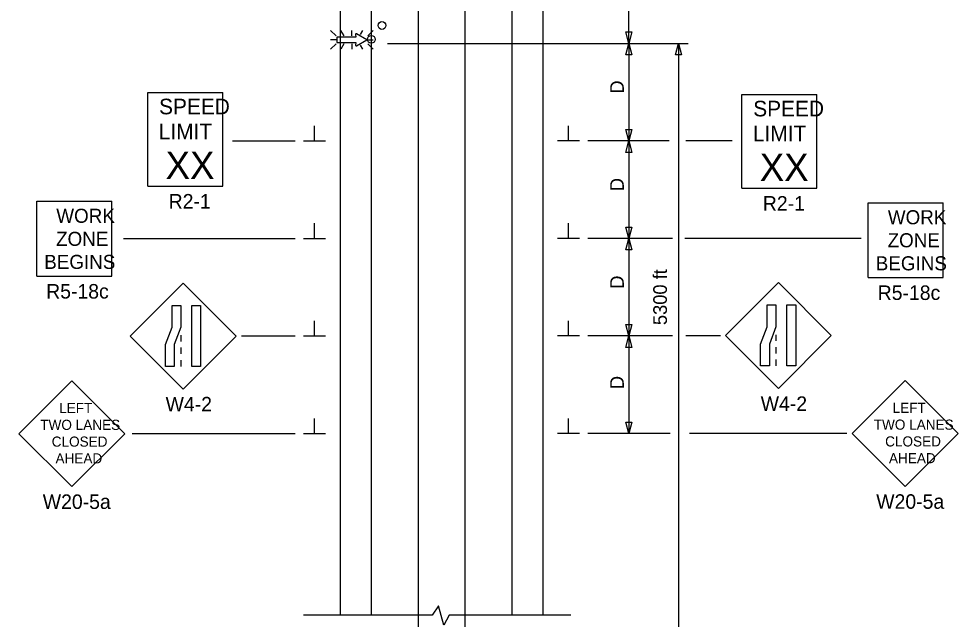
# Model space of a CAD drawing. Extents: x 16794 to 19504, y 7009 to 8243.
# Drawn here: x 17851.7 to 18333.2, y 7552.3 to 7860.1 of the extents above; entities that cross this region are included whole.
import ezdxf

# ---------------------------------------------------------------- set-up
doc = ezdxf.new("R2010")
doc.units = 0
for name, color, linetype in [('ALI_LEGAL_EX', 7, 'Continuous'), ('PAVT_EDGE_EX', 7, 'Continuous'), ('TRAFFIC_SIGNS_PR', 7, 'Continuous'), ('TYPICAL_TEXT_DIMEN_PR', 7, 'Continuous')]:
    doc.layers.add(name, color=color, linetype=linetype)

msp = doc.modelspace()

# ---------------------------------------------------------------- linework, layer by layer
at = {"layer": 'ALI_LEGAL_EX'}
for p, q in [((18056.37, 8191.42), (18056.37, 7362.23)), ((18080.37, 8191.42), (18080.37, 7362.23)), ((18080.37, 8191.42), (18080.37, 7362.23))]:
    msp.add_line(p, q, dxfattribs=at)
for points in [[(18056.37, 7791.42), (18056.37, 7766.42)], [(18080.37, 7791.42), (18080.37, 7766.42)], [(18056.37, 7691.42), (18056.37, 7666.42)], [(18080.37, 7691.42), (18080.37, 7666.42)], [(18056.37, 7591.42), (18056.37, 7566.42)], [(18080.37, 7591.42), (18080.37, 7566.42)]]:
    msp.add_lwpolyline(points, dxfattribs=at)
at = {"layer": 'PAVT_EDGE_EX'}
for p, q in [((18016.37, 8214.7), (18016.37, 7554.34)), ((18032.37, 8214.7), (18032.37, 7554.34)), ((18104.37, 8214.7), (18104.37, 7554.34)), ((18120.37, 8214.7), (18120.37, 7554.34))]:
    msp.add_line(p, q, dxfattribs=at)
at = {"layer": 'TRAFFIC_SIGNS_PR'}
for p, q in [((18014.39, 7851.34), (18011.56, 7854.16)), ((18016.68, 7854.16), (18018.31, 7851.34)), ((18022.47, 7851.34), (18022.47, 7854.16)), ((18027.94, 7854.16), (18026.73, 7852.06)), ((18033.37, 7854.15), (18030.56, 7851.34)), ((18014.39, 7849.31), (18011.56, 7849.31)), ((18030.56, 7849.31), (18033.37, 7849.31)), ((18014.39, 7847.27), (18011.56, 7844.45)), ((18018.33, 7847.27), (18016.71, 7844.45)), ((18022.47, 7847.27), (18022.47, 7844.45)), ((18026.65, 7846.64), (18027.91, 7844.45)), ((18033.37, 7844.45), (18030.56, 7847.27)), ((17917.86, 7822.26), (17956.26, 7822.26)), ((17917.86, 7774.26), (17917.86, 7822.26)), ((17956.26, 7774.26), (17956.26, 7822.26)), ((18222.36, 7821.2), (18260.76, 7821.2)), ((18222.36, 7773.2), (18222.36, 7821.2)), ((18260.76, 7773.2), (18260.76, 7821.2)), ((17917.86, 7774.26), (17956.26, 7774.26)), ((18222.36, 7773.2), (18260.76, 7773.2)), ((17860.95, 7728.12), (17860.95, 7766.52)), ((17860.95, 7766.52), (17899.35, 7766.52)), ((17899.35, 7728.12), (17899.35, 7766.52)), ((18287.1, 7727.4), (18287.1, 7765.8)), ((18287.1, 7765.8), (18325.5, 7765.8)), ((18325.5, 7727.4), (18325.5, 7765.8)), ((17860.95, 7728.12), (17899.35, 7728.12)), ((18287.1, 7727.4), (18325.5, 7727.4)), ((17936.01, 7724.58), (17908.86, 7697.43)), ((17963.16, 7697.43), (17936.01, 7724.58)), ((18241, 7724.84), (18213.85, 7697.68)), ((18268.15, 7697.68), (18241, 7724.84)), ((17908.86, 7697.43), (17936.01, 7670.28)), ((17934.76, 7697.92), (17934.76, 7694.72)), ((17936.01, 7670.28), (17963.16, 7697.43)), ((18213.85, 7697.68), (18241, 7670.53)), ((18239.75, 7698.17), (18239.75, 7694.97)), ((18241, 7670.53), (18268.15, 7697.68)), ((17934.76, 7691.52), (17934.76, 7688.32)), ((18239.75, 7691.77), (18239.75, 7688.57)), ((17934.76, 7685.12), (17934.76, 7681.92)), ((18239.75, 7685.37), (18239.75, 7682.17)), ((17878.88, 7674.57), (17851.73, 7647.42)), ((17906.04, 7647.42), (17878.88, 7674.57)), ((18306.02, 7674.66), (18278.87, 7647.51)), ((18333.17, 7647.51), (18306.02, 7674.66)), ((17851.73, 7647.42), (17878.88, 7620.27)), ((17878.88, 7620.27), (17906.04, 7647.42)), ((18278.87, 7647.51), (18306.02, 7620.36)), ((18306.02, 7620.36), (18333.17, 7647.51))]:
    msp.add_line(p, q, dxfattribs=at)
for points in [[(18024.8, 7846.29), (18030.11, 7849.31), (18024.8, 7852.35)], [(18024.3, 7851.99), (18024.53, 7850.69), (18014.8, 7850.69), (18014.8, 7847.95), (18024.53, 7847.95), (18024.3, 7846.64)]]:
    msp.add_lwpolyline(points, dxfattribs=at)
for points in [[(17934.76, 7713.17), (17934.76, 7701.99), (17931.42, 7693.1), (17931.42, 7681.92), (17926.92, 7681.92), (17926.92, 7693.1), (17930.27, 7701.99), (17930.27, 7713.17)], [(17944.9, 7713.17), (17944.9, 7681.92), (17940.4, 7681.92), (17940.4, 7713.17)], [(18239.75, 7713.42), (18239.75, 7702.24), (18236.41, 7693.36), (18236.41, 7682.17), (18231.91, 7682.17), (18231.91, 7693.36), (18235.26, 7702.24), (18235.26, 7713.42)], [(18249.89, 7713.42), (18249.89, 7682.17), (18245.39, 7682.17), (18245.39, 7713.42)]]:
    msp.add_lwpolyline(points, close=True, dxfattribs=at)
for centre in [(18037.87, 7856.66), (18032.38, 7849.54)]:
    msp.add_circle(centre, 2, dxfattribs=at)
for centre, start, end in [((18024.63, 7852.05), 61.4833, 189.9593), ((18024.63, 7846.59), 170.7308, 298.8916)]:
    msp.add_arc(centre, 0.341, start, end, dxfattribs=at)
at = {"layer": 'TYPICAL_TEXT_DIMEN_PR'}
for p, q in [((18164.37, 7847.49), (18164.37, 7878.05)), ((18164.37, 7847.49), (18162.8, 7853.35)), ((18162.8, 7853.35), (18164.37, 7853.35)), ((18164.37, 7853.35), (18165.94, 7853.35)), ((18165.94, 7853.35), (18164.37, 7847.49)), ((18040.76, 7847.49), (18194.8, 7847.49)), ((18162.8, 7841.63), (18164.37, 7847.49)), ((18164.37, 7847.49), (18164.37, 7797.49)), ((18164.37, 7847.49), (18165.94, 7841.63)), ((18188.23, 7841.63), (18189.8, 7847.49)), ((18189.8, 7847.49), (18189.8, 7497.49)), ((18189.8, 7847.49), (18191.37, 7841.63)), ((18164.37, 7841.63), (18162.8, 7841.63)), ((18165.94, 7841.63), (18164.37, 7841.63)), ((18189.8, 7841.63), (18188.23, 7841.63)), ((18191.37, 7841.63), (18189.8, 7841.63)), ((18003.24, 7797.49), (18003.24, 7805.27)), ((18003.24, 7797.49), (18003.24, 7805.27)), ((18133.49, 7797.49), (18133.49, 7805.27)), ((18164.37, 7797.49), (18162.8, 7803.35)), ((18162.8, 7803.35), (18164.37, 7803.35)), ((18164.37, 7803.35), (18165.94, 7803.35)), ((18165.94, 7803.35), (18164.37, 7797.49)), ((17961.23, 7797.49), (17993.37, 7797.49)), ((17997.62, 7797.49), (18008.87, 7797.49)), ((17997.62, 7797.49), (18008.87, 7797.49)), ((18139.12, 7797.49), (18127.87, 7797.49)), ((18184.98, 7797.49), (18143.37, 7797.49)), ((18162.79, 7791.63), (18164.37, 7797.49)), ((18164.37, 7797.49), (18164.37, 7747.49)), ((18164.37, 7797.49), (18165.94, 7791.63)), ((18217.33, 7797.49), (18193.51, 7797.49)), ((18164.37, 7791.63), (18162.79, 7791.63)), ((18165.94, 7791.63), (18164.37, 7791.63)), ((18003.24, 7747.49), (18003.24, 7755.27)), ((18003.24, 7747.49), (18003.24, 7755.27)), ((18133.49, 7747.49), (18133.49, 7755.27)), ((18164.37, 7747.49), (18162.8, 7753.35)), ((18162.8, 7753.35), (18164.37, 7753.35)), ((18164.37, 7753.35), (18165.94, 7753.35)), ((18165.94, 7753.35), (18164.37, 7747.49)), ((17905.42, 7747.49), (17993.37, 7747.49)), ((17987.28, 7747.49), (17993.37, 7747.49)), ((17997.62, 7747.49), (18008.87, 7747.49)), ((17997.62, 7747.49), (18008.87, 7747.49)), ((18139.12, 7747.49), (18127.87, 7747.49)), ((18186.8, 7747.49), (18143.37, 7747.49)), ((18162.79, 7741.63), (18164.37, 7747.49)), ((18164.37, 7747.49), (18164.37, 7697.49)), ((18164.37, 7747.49), (18165.94, 7741.63)), ((18283.38, 7747.49), (18193.03, 7747.49)), ((18164.37, 7741.63), (18162.79, 7741.63)), ((18165.94, 7741.63), (18164.37, 7741.63)), ((18003.24, 7697.49), (18003.24, 7705.27)), ((18003.24, 7697.49), (18003.24, 7705.27)), ((18133.49, 7697.49), (18133.49, 7705.27)), ((18164.37, 7697.49), (18162.8, 7703.35)), ((18162.8, 7703.35), (18164.37, 7703.35)), ((18164.37, 7703.35), (18165.94, 7703.35)), ((18165.94, 7703.35), (18164.37, 7697.49)), ((17965.81, 7697.49), (17993.37, 7697.49)), ((17997.62, 7697.49), (18008.87, 7697.49)), ((17997.62, 7697.49), (18008.87, 7697.49)), ((18139.12, 7697.49), (18127.87, 7697.49)), ((18186.8, 7697.49), (18143.37, 7697.49)), ((18162.79, 7691.63), (18164.37, 7697.49)), ((18164.37, 7697.49), (18164.37, 7647.49)), ((18164.37, 7697.49), (18165.94, 7691.63)), ((18211.33, 7697.49), (18193.51, 7697.49)), ((18164.37, 7691.63), (18162.79, 7691.63)), ((18165.94, 7691.63), (18164.37, 7691.63)), ((18003.24, 7647.49), (18003.24, 7655.27)), ((18133.49, 7647.49), (18133.49, 7655.27)), ((18164.37, 7647.49), (18162.79, 7653.35)), ((18162.79, 7653.35), (18164.37, 7653.35)), ((18164.37, 7653.35), (18165.94, 7653.35)), ((18165.94, 7653.35), (18164.37, 7647.49)), ((17909.81, 7647.49), (17993.37, 7647.49)), ((17997.62, 7647.49), (18008.87, 7647.49)), ((18139.12, 7647.49), (18127.87, 7647.49)), ((18185.59, 7647.49), (18143.37, 7647.49)), ((18276.02, 7647.49), (18195.42, 7647.49)), ((18066.88, 7559.14), (18063.62, 7554.34)), ((18069.62, 7549.2), (18066.88, 7559.14)), ((18063.62, 7554.34), (17997.68, 7554.34)), ((18072.36, 7554.34), (18069.62, 7549.2)), ((18134.69, 7554.34), (18072.36, 7554.34))]:
    msp.add_line(p, q, dxfattribs=at)

# ---------------------------------------------------------------- texts
at = {"layer": 'TRAFFIC_SIGNS_PR'}
for s, height, p in [('SPEED', 8, (17923.63, 7811.12)), ('SPEED', 8, (18228.13, 7810.06)), ('LIMIT', 8, (17923.47, 7798.32)), ('LIMIT', 8, (18227.96, 7797.26)), ('XX', 14.031, (17926.98, 7778.01)), ('XX', 14.031, (18231.47, 7776.96)), ('R2-1', 7.44, (17928.54, 7762.82)), ('R2-1', 7.44, (18233.04, 7761.76)), ('WORK', 7.217, (17870.95, 7755.49)), ('WORK', 7.217, (18297.1, 7754.76)), ('ZONE', 7.217, (17870.83, 7743.68)), ('ZONE', 7.217, (18296.98, 7742.95)), ('BEGINS', 7.217, (17864.76, 7731.87)), ('BEGINS', 7.217, (18290.91, 7731.14)), ('R5-18c', 7.44, (17865.76, 7716.68)), ('R5-18c', 7.44, (18291.91, 7715.96)), ('W4-2', 7.44, (17926.97, 7658.84)), ('W4-2', 7.44, (18231.96, 7659.09)), ('LEFT', 5.2, (17872.42, 7657.95)), ('LEFT', 5.2, (18299.56, 7658.05)), ('TWO LANES', 5.2, (17862.74, 7649.35)), ('TWO LANES', 5.2, (18289.88, 7649.45)), ('CLOSED', 5.2, (17868.6, 7640.75)), ('CLOSED', 5.2, (18295.73, 7640.85)), ('AHEAD', 5.2, (17870.54, 7632.15)), ('AHEAD', 5.2, (18297.68, 7632.25)), ('W20-5a', 7.44, (18291.16, 7608.92)), ('W20-5a', 7.44, (17864.02, 7608.83))]:
    msp.add_text(s, height=height, dxfattribs=at).set_placement(p)
at = {"layer": 'TYPICAL_TEXT_DIMEN_PR'}
for s, p in [('D', (18161.81, 7821.71)), ('D', (18161.81, 7771.71)), ('D', (18161.81, 7721.71)), ('5300 ft', (18183.89, 7703.09)), ('D', (18161.81, 7670.27))]:
    msp.add_text(s, height=7, rotation=90, dxfattribs=at).set_placement(p)

doc.saveas('drawing.dxf')
